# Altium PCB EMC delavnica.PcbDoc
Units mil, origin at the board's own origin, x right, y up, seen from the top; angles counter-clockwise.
Board outline 3937.01 x 3937.01 mil, 2 copper layers (Top Layer, Bottom Layer); 19 components, 17 nets, 67 pads, 1 vias.
Unrouted connection lines stored in the file: 27.
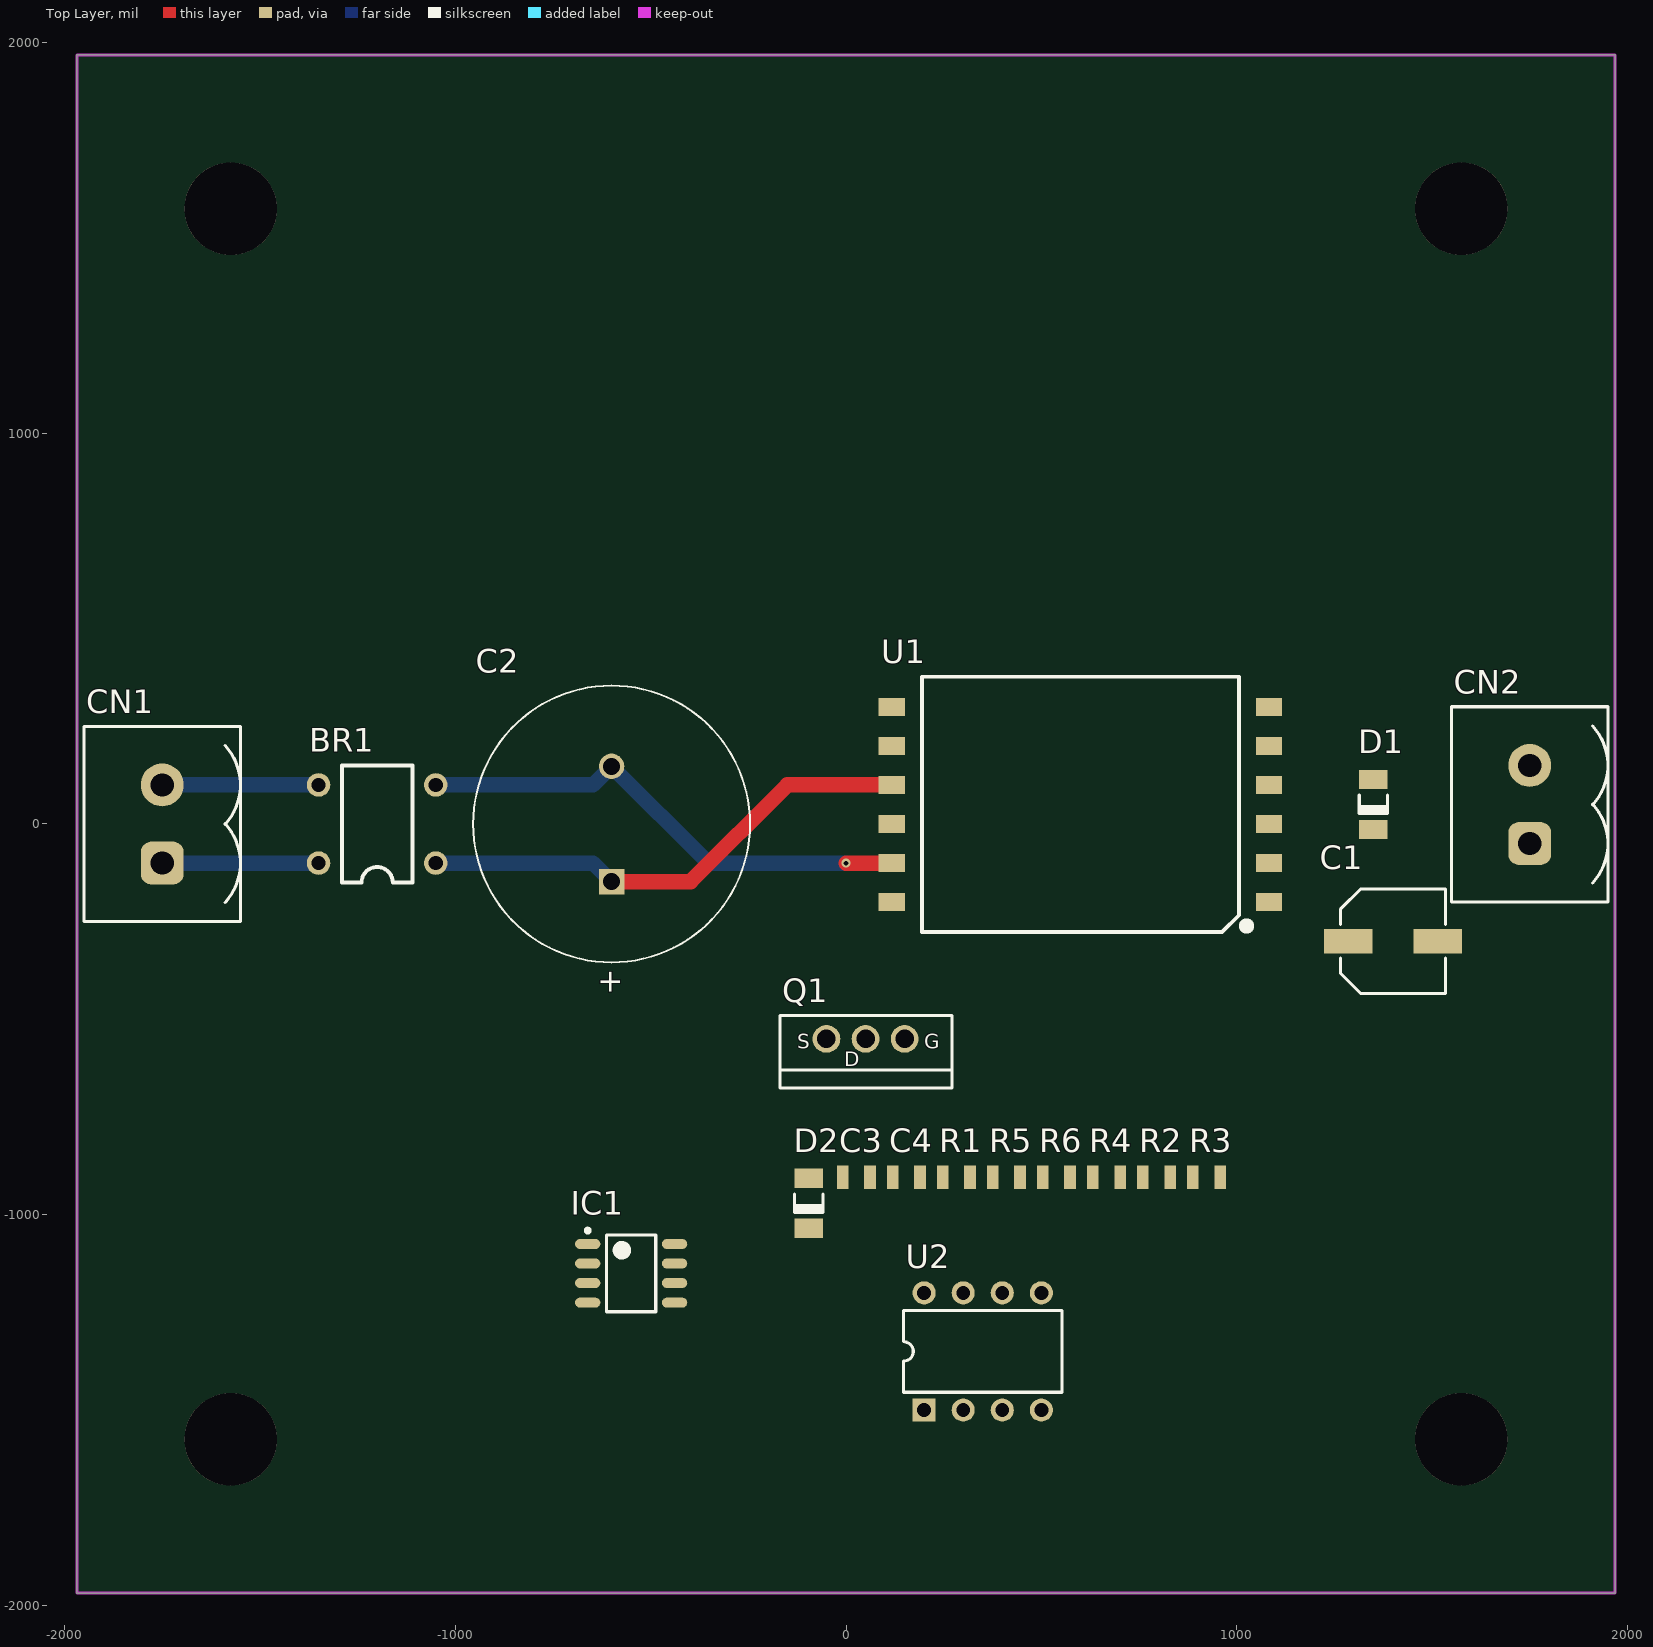
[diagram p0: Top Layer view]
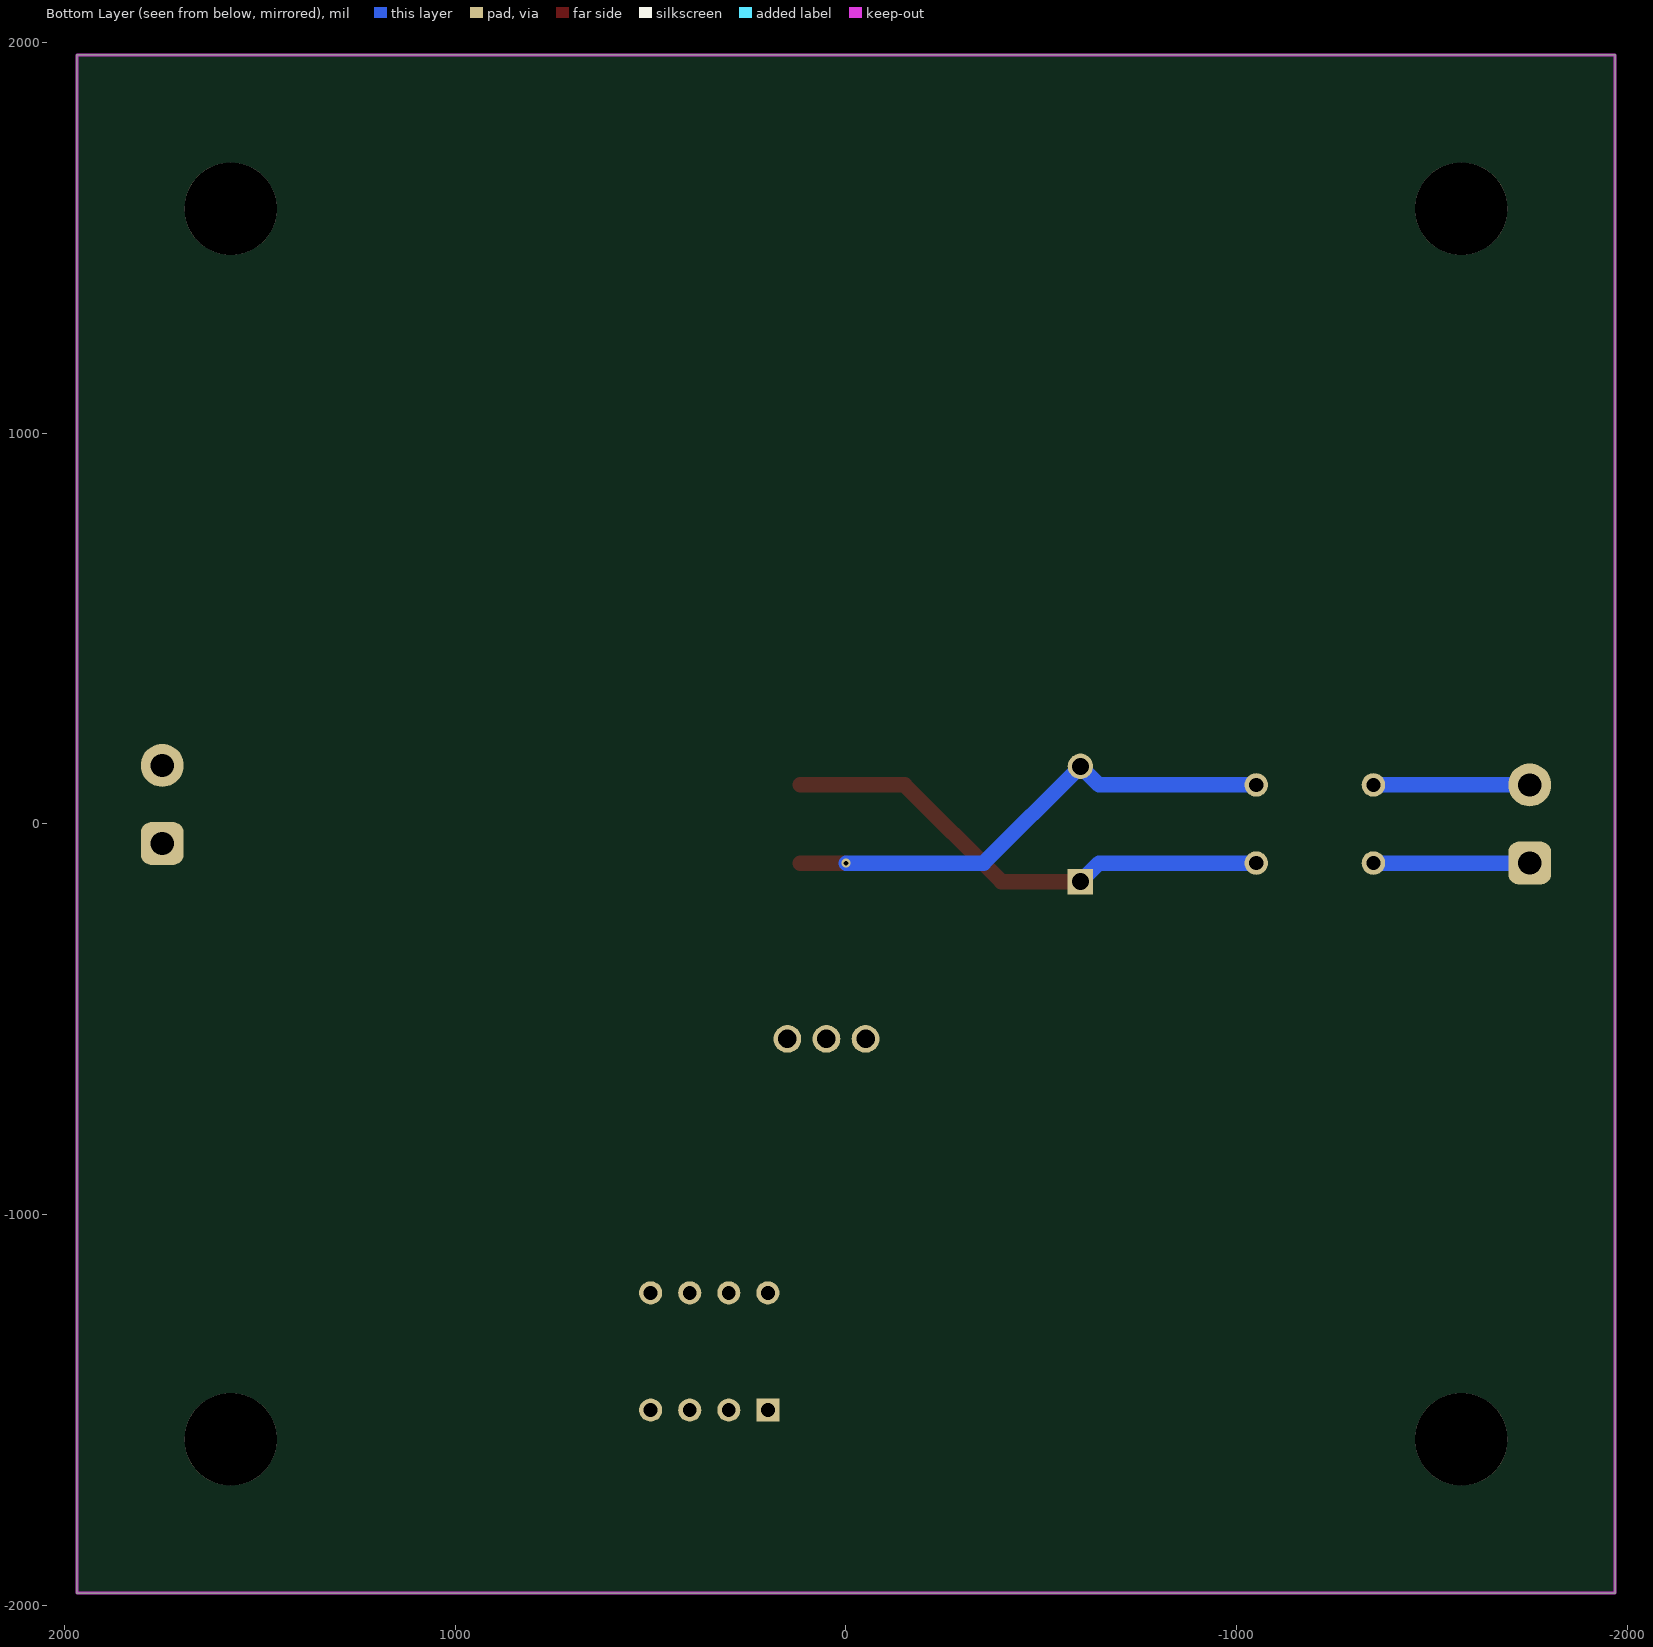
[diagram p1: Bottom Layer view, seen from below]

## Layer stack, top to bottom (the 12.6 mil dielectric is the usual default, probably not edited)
Top Solder: solder mask 0.4, Solder Resist, Dk 3.5
Top Layer: signal copper 1.4
Dielectric 1: dielectric 12.6, FR-4, Dk 4.8
Bottom Layer: signal copper 1.4
Bottom Solder: solder mask 0.4, Solder Resist, Dk 3.5

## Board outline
-1968.5,-1968.5 1968.5,-1968.5 1968.5,1968.5 -1968.5,1968.5

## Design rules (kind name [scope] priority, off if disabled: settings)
Clearance [All] p1: gap=7.87 ignorepadtopadclearanceinfootprint=FALSE
Clearance Clearance_HighV [InNetClass('HighV')] p2: gap=78.74 ignorepadtopadclearanceinfootprint=FALSE
Height [All] p1: minheight=0 maxheight=39370.08 prefheight=500
PolygonConnect [All] p1: connectstyle=Relief reliefconductorwidth=10 reliefentries=4 polygonreliefangle="90 Angle" airgapwidth=10
RoutingVias [All] p1: holewidth=15.75 width=31.5 viastyle="Through Hole" minholewidth=11.81 minwidth=23.62 maxholewidth=23.62 maxwidth=47.24
SolderMaskExpansion [All] p1: expansion=4
Width [All] p1: maxlimit=393.7 minlimit=7.87 preferedwidth=11.81
29 further rules are at their usual default settings.

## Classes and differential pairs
net class HighV: NetBR1_AC1 NetBR1_AC2 NetBR1_PLUS NetQ1_D

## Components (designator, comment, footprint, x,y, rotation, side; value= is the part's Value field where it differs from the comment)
BR1 "B250C800D" DIP4M-GREZ -1050,-100 r180 top value={Value}
C1 "{Value}" C-SMD-ELKO-D 1400,-300 r0 top
C2 "100 uF" WCAP-ATG8_18x31.5x7.5x0.8 -600,0 r270 top
C3 "{Value}" C0805 26.58,-904 r0 top
C4 "{Value}" C0805 154.58,-904 r0 top
CN1 "K2PH_M_TOP" K2PH_M_TOP -1750,-100 r180 top value={Value}
CN2 "K2PH_M_TOP" K2PH_M_TOP 1750,-50 r180 top value={Value}
D1 "1N4148" MELF3517N_DIO 1350,50 r90 top
D2 "1N4148" MELF3517N_DIO -95.65,-970.39 r90 top
IC1 "UCC28600" SOIC127P600X175-8M -550,-1150 r0 top
Q1 "IRF512" "TO-220AB vertical" 50,-550 r0 top value={Value}
R1 "{Value}" R0805 282.58,-904 r0 top
R2 "{Value}" R0805 794.58,-904 r0 top
R3 "{Value}" R0805 922.58,-904 r0 top
R4 "{Value}" R0805 666.58,-904 r0 top
R5 "{Value}" R0805 410.58,-904 r0 top
R6 "{Value}" R0805 538.58,-904 r0 top
U1 "760871113" WE-UOST_EE16/8/5 600,50 r180 top
U2 "ILD74" DIP8 350,-1350 r0 top

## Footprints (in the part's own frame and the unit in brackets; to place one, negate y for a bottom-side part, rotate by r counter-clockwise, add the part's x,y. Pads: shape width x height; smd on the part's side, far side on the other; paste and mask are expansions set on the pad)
C0805 [mil]
  rect 30x60 smd: 1(-35,0) 2(35,0)
  body extent -39,-25 39,24, height 31
C-SMD-ELKO-D [mm]
  rect 3.15x1.6 smd: 1(-2.9,0) 2(2.9,0)
  silkscreen extent -3.4,-3.4 3.4,3.4, body extent -3.5,-3.3 3.5,3.3, height 5.4
DIP4M-GREZ [mil]
  round 60 hole 36: AC1(300,0) AC2(300,-200) GND(0,-200) PLUS(0,0)
  silkscreen extent 60,-250 240,50, body extent -9,-251 305,53, height 138
DIP8 [mm]
  rect 1.5x1.5 hole 0.9: 1(-3.81,-3.81)
  round 1.5 hole 0.9: 2(-1.27,-3.81) 3(1.27,-3.81) 4(3.81,-3.81) 5(3.81,3.81) 6(1.27,3.81) 7(-1.27,3.81) 8(-3.81,3.81)
  silkscreen extent -5.15,-2.65 5.15,2.65
K2PH_M_TOP [mil]
  rrect50% 110x110 hole 59: 1(0,0)
  round 110 hole 59: 2(0,-200)
  silkscreen extent -200,-350 200,150
MELF3517N_DIO [mm]
  rect 1.25x1.85 smd: 1(-1.625,0) 2(1.625,0)
  silkscreen extent -0.6,-0.93 0.6,0.92, body extent -1.72,-0.76 1.78,0.74, height 1.5
R0805 [mil]
  rect 30x60 smd: 1(-35,0) 2(35,0)
  body extent -39,-25 39,24, height 31
SOIC127P600X175-8M [mm] "SOIC, 8-Leads, Body 4.90x3.90mm, Pitch 1.27mm, IPC Low Density"
  oval 1.65x0.65 smd: 1(-2.825,1.905) 2(-2.825,0.635) 3(-2.825,-0.635) 4(-2.825,-1.905) 5(2.825,-1.905) 6(2.825,-0.635) 7(2.825,0.635) 8(2.825,1.905)
  silkscreen extent -2.95,-2.5 1.6,2.9, body extent -3,-2.5 3,2.5, height 1.75
"TO-220AB vertical" [mm]
  round 1.8 hole 1.2: D(0,0) G(2.54,0) S(-2.54,0)
  silkscreen extent -5.56,-3.2 5.63,1.52, body extent -5.58,-3.19 5.63,1.5, height 19.33
WCAP-ATG8_18x31.5x7.5x0.8 [mm]
  rect 1.65x1.65 hole 1.1: 1(3.75,0)
  round 1.65 hole 1.1: 2(-3.75,0)
  silkscreen extent -9,-9 9,9, body extent -8.99,-9 8.93,8.95, height 31.61
WE-UOST_EE16/8/5 [mm]
  rect 1.7x1.17 smd: 1(-12.265,6.35) 2(-12.265,3.81) 3(-12.265,1.27) 4(-12.265,-1.27) 5(-12.265,-3.81) 6(-12.265,-6.35) 7(12.265,-6.35) 8(12.265,-3.81) 9(12.265,-1.27) 10(12.265,1.27) 11(12.265,3.81) 12(12.265,6.35)
  silkscreen extent -10.9,-8.3 10.3,8.3, body extent -12.9,-8.3 12.91,8.3, height 13.5

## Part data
C1: library part C+, "Capacitor Polarized"
C2: library part "WCAP-ATG8, 860011381012", "WCAP-ATG8 Aluminum Electrolytic Capacitors, 100 uF", PartNumber=860011381012, RatedVoltage=400V
C3 C4: library part C, "Capacitor"
IC1: "Flyback power supply controller from TI"
R1 R2 R3 R4 R5 R6: library part R, "R"
U1: "WE-UOST Universal Offline Standard Transformers, size EE16/8/5, 1310 uH , 140:6:6:16 , 12.5 W", Inductance="1310 uH", OutputPower="12.5 W"
U2: "Optocoupler, Phototransistor Output, Dual Channel, TTL Compatible, Pb-free", PackageDocument=Dec-2003

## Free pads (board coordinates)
  round 236.22 hole 236.22: 1(-1574.8,1574.8) 2(1574.8,1574.8) 3(1574.8,-1574.8) 4(-1574.8,-1574.8)

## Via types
v1: diameter 23.62, hole 11.81, Top Layer to Bottom Layer, 1 vias

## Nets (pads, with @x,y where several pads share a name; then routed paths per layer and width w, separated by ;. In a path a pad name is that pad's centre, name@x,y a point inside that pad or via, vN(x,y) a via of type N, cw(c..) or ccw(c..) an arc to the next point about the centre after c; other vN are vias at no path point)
GND: BR1.GND C2.2 C3.2 C4.1 IC1.4 R4.2 R6.2 U1.11 U2.8 | length 1289.4
  Top Layer w39.37: v1(0,-100) U1.11
  Bottom Layer w39.37: BR1.GND -647.64,100 C2.2 -352.36,-100 v1(0,-100)
NetBR1_AC1: BR1.AC1 CN1.1 | length 400
  Bottom Layer w39.37: CN1.1 BR1.AC1
NetBR1_AC2: BR1.AC2 CN1.2 | length 400
  Bottom Layer w39.37: CN1.2 BR1.AC2
NetBR1_PLUS: BR1.PLUS C2.1 R1.1 U1.9 | length 1289.4
  Top Layer w39.37: C2.1 -397.64,-147.64 -150,100 U1.9
  Bottom Layer w39.37: BR1.PLUS -647.64,-100 C2.1
NetC1_1: C1.1 CN2.1 D1.1
NetC3_1: C3.1 IC1.6 R1.2 R2.1
NetC4_2: C4.2 IC1.1
NetD1_A: D1.2 U1.4
NetD2_A: D2.2 R3.1 U1.12
NetD2_K: D2.1 R2.2
NetIC1_2: IC1.2 U2.7
NetIC1_3: IC1.3 R5.1
NetIC1_5: IC1.5 Q1.G
NetIC1_7: IC1.7 R3.2 R4.1
NetQ1_D: Q1.D U1.7
NetQ1_S: Q1.S R5.2 R6.1
SEC_GND: C1.2 CN2.2 U1.1
pads on no net: IC1.8 U1.2 U1.3 U1.5 U1.6 U1.8 U1.10 U2.1 U2.2 U2.3 U2.4 U2.5 U2.6

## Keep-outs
Keep-Out Layer:
  the board outline again, w7.87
